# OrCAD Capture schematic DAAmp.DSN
size A; title: Release Design; rev: A; company: Parallel Systems Ltd.; note: 9875477612; note: PO Box 4265; note: Bracknell
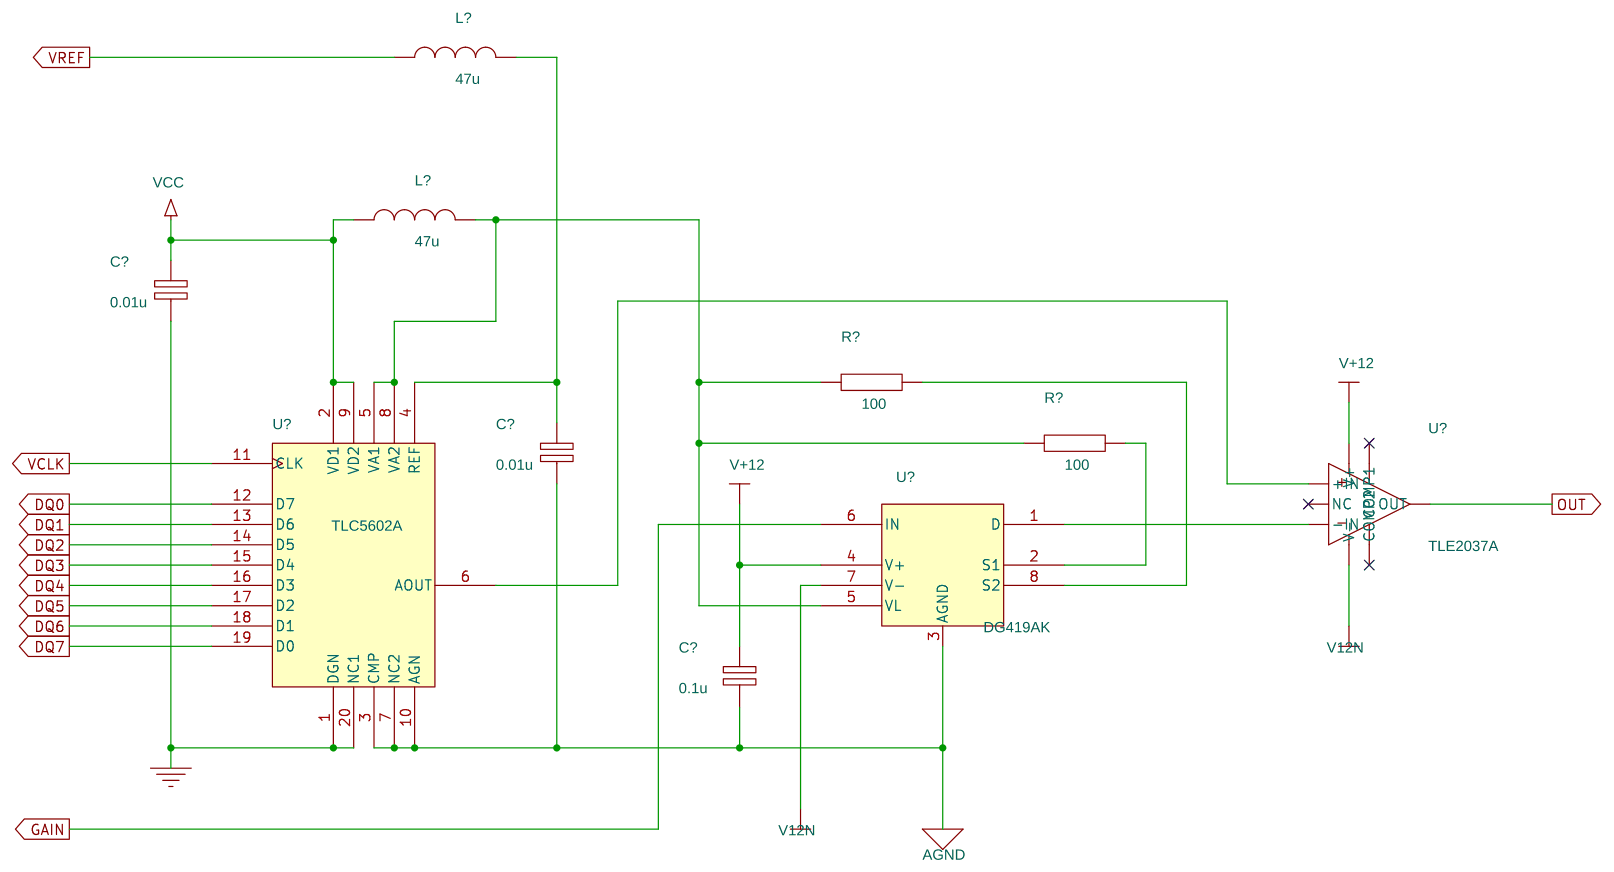
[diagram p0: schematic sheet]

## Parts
C?#3  0.1u  [SM_1206]
C?#6  0.01u  [SM_1206]
C?#8  0.01u  [SM_1206]
L?#1  47u  [IND300]
L?#7  47u  [IND300]
R?#9  100  [SM_0805]
R?#10  100  [SM_0805]
U?#2  DG419AK  [SOIC8]
U?#4  TLE2037A  [TO-99]
U?#5  TLC5602A  [SOIC20]

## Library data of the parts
C?#3 C?#6 C?#8 = CAP_NP: CLASS: DISCRETE
L?#1 L?#7 = INDUCTOR: CLASS: DISCRETE
R?#9 R?#10 = R: CLASS: DISCRETE
U?#2 = DG419AK: CLASS: IC
U?#4 = TLE2037A: CLASS: IC
U?#5 = TLC5602A: CLASS: IC

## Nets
AGND: C?#3.2 C?#6.2 U?#2.3(AGND) U?#5.3(CMP) U?#5.7(NC2) U?#5.10(AGN)
GND: C?#8.2 U?#5.1(DGN) U?#5.20(NC1)
V12N: U?#2.7(V-) U?#4.4(V-)
VCC: C?#8.1 L?#1.1 U?#5.2(VD1) U?#5.9(VD2)
DQ0: U?#5.12(D7)
DQ1: U?#5.13(D6)
DQ2: U?#5.14(D5)
DQ3: U?#5.15(D4)
DQ4: U?#5.16(D3)
DQ5: U?#5.17(D2)
DQ6: U?#5.18(D1)
DQ7: U?#5.19(D0)
GAIN: U?#2.6(IN)
OUT: U?#4.6(OUT)
V+12: C?#3.1 U?#2.4(V+) U?#4.7(V+)
VCLK: U?#5.11(CLK)
VREF: L?#7.1
N00036: L?#1.2 R?#9.1 R?#10.1 U?#2.5(VL) U?#5.5(VA1) U?#5.8(VA2)
N00038: C?#6.1 L?#7.2 U?#5.4(REF)
N00044: U?#2.1(D) U?#4.2(-IN)
N00060: U?#4.3(+IN) U?#5.6(AOUT)
N282866: R?#10.2 U?#2.8(S2)
N282912: R?#9.2 U?#2.2(S1)

Not connected (* = marked no-connect by the designer): U?#4 1(COMP1)* 5(NC)* 8(COMP2)*
